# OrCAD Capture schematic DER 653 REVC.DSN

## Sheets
1 Misc: size A
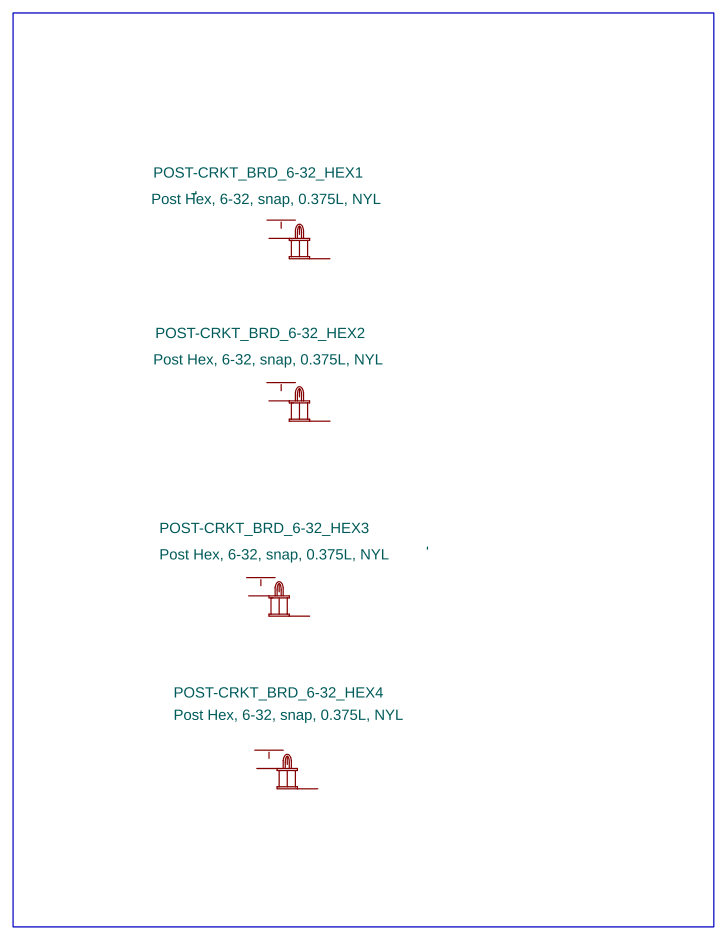
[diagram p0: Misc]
2 CONTROLLER AND INVERTER CKT: size D
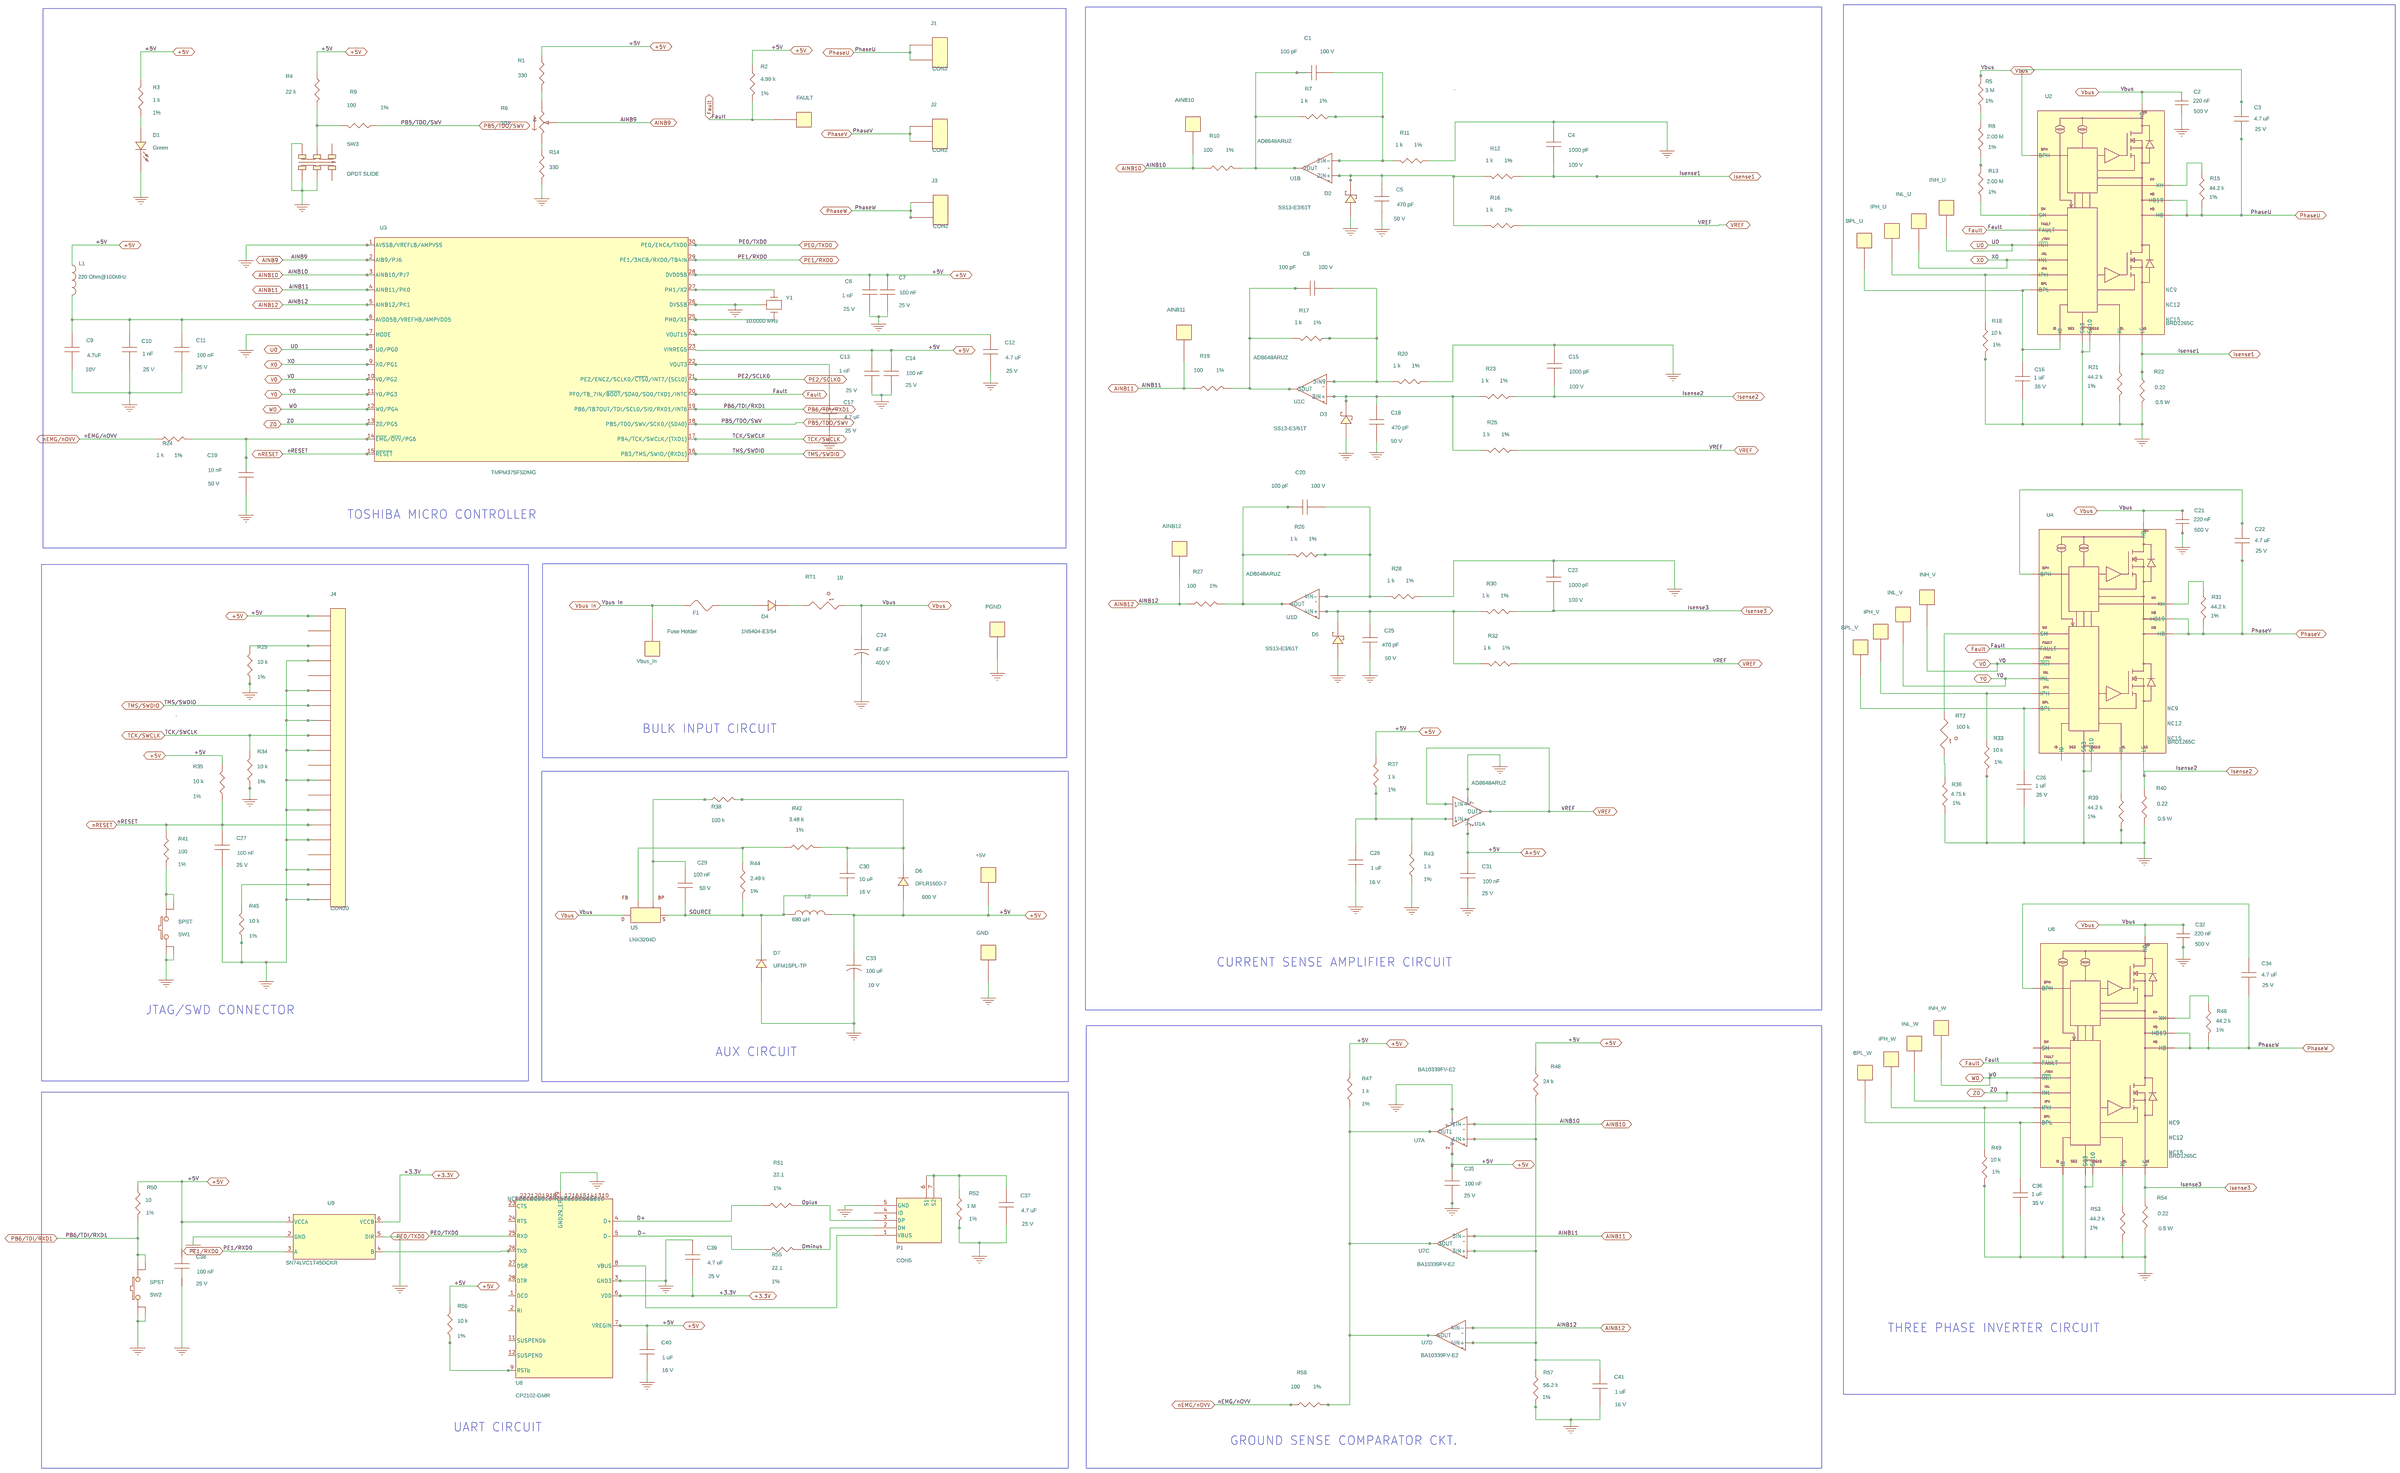
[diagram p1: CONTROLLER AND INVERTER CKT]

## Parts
sheet CONTROLLER AND INVERTER CKT
+5V  CON1  [pi_MillMax030d]
AINB10  CON1  [pi_MillMax030d]
AINB11  CON1  [pi_MillMax030d]
AINB12  CON1  [pi_MillMax030d]
BPL_U  CON1  [pi_MillMax030d]
BPL_V  CON1  [pi_MillMax030d]
BPL_W  CON1  [pi_MillMax030d]
C1  100 pF  [pismc0805]
C2  220 nF  [pismc1812]
C3  4.7 uF  [pismc1206]
C4  1000 pF  [pismc0603]
C5  470 pF  [pismc0603]
C6  1 nF  [pismc0603]
C7  100 nF  [pismc0603]
C8  100 pF  [pismc0805]
C9  4.7uF  [pismc0603]
C10  1 nF  [pismc0603]
C11  100 nF  [pismc0603]
C12  4.7 uF  [pismc0805]
C13  1 nF  [pismc0603]
C14  100 nF  [pismc0603]
C15  1000 pF  [pismc0603]
C16  1 uF  [pismc0603]
C17  4.7 uF  [pismc0805]
C18  470 pF  [pismc0603]
C19  10 nF  [pismc0603]
C20  100 pF  [pismc0805]
C21  220 nF  [pismc1812]
C22  4.7 uF  [pismc1206]
C23  1000 pF  [pismc0603]
C24  47 uF  [pipolcapclyd710ls300040]
C25  470 pF  [pismc0603]
C26  1 uF  [pismc0603]
C27  100 nF  [pismc0603]
C28  1 uF  [pismc0603]
C29  100 nF  [pismc0603]
C30  10 uF  [pismc0805]
C31  100 nF  [pismc0603]
C32  220 nF  [pismc1812]
C33  100 uF  [pipolcapclyd200ls80030]
C34  4.7 uF  [pismc1206]
C35  100 nF  [pismc0603]
C36  1 uF  [pismc0603]
C37  4.7 uF  [pismc0805]
C38  100 nF  [pismc0603]
C39  4.7 uF  [pismc0805]
C40  1 uF  [pismc0603]
C41  1 uF  [pismc0603]
D1  Green  [pi_sm_d_0603]
D2  SS13-E3/61T  [pismdo214ac12]
D3  SS13-E3/61T  [pismdo214ac12]
D4  1N5404-E3/54  [pidv300x200x060do15d0201ad]
D5  SS13-E3/61T  [pismdo214ac12]
D6  DFLR1600-7  [pismddflr120012]
D7  UFM15PL-TP  [pi_sm_sod-123_12]
F1  Fuse Holder  [fuse_e]
FAULT  CON1  [pi_MillMax030d]
GND  CON1  [pi_MillMax030d]
INH_U  CON1  [pi_MillMax030d]
INH_V  CON1  [pi_MillMax030d]
INH_W  CON1  [pi_MillMax030d]
INL_U  CON1  [pi_MillMax030d]
INL_V  CON1  [pi_MillMax030d]
INL_W  CON1  [pi_MillMax030d]
IPH_U  CON1  [pi_MillMax030d]
IPH_V  CON1  [pi_MillMax030d]
IPH_W  CON1  [pi_MillMax030d]
J1  CON2  [pi_conn_qc_tab_2pin_ls200]
J2  CON2  [pi_conn_qc_tab_2pin_ls200]
J3  CON2  [pi_conn_qc_tab_2pin_ls200]
J4  CON20  [pi_20p_2x10_Shrouded]
L1  220 Ohm@100MHz  [INDC2012X105N]
L2  680 uH  [pichoketokinvd345h453ls197d030]
P1  CON5  [TE_CONNECTIVITY_1734510-1]
PGND  CON1  [pi_MillMax030d]
R1  330  [pismr0603]
R2  4.99 k  [pismr0805]
R3  1 k  [pismr0603]
R4  22 k  [pismr0603]
R5  3 M  [pismr1206]
R6  10 k  [pi_vres_vertadj]
R7  1 k  [pismr0603]
R8  2.00 M  [pismr1206]
R9  100  [pismr0603]
R10  100  [pismr0603]
R11  1 k  [pismr0603]
R12  1 k  [pismr0603]
R13  2.00 M  [pismr1206]
R14  330  [pismr0603]
R15  44.2 k  [pismr0603]
R16  1 k  [pismr0603]
R17  1 k  [pismr0603]
R18  10 k  [pismr0603]
R19  100  [pismr0603]
R20  1 k  [pismr0603]
R21  44.2 k  [pismr0603]
R22  0.22  [pismr2010]
R23  1 k  [pismr0603]
R24  1 k  [pismr0603]
R25  1 k  [pismr0603]
R26  1 k  [pismr0603]
R27  100  [pismr0603]
R28  1 k  [pismr0603]
R29  10 k  [pismr0603]
R30  1 k  [pismr0603]
R31  44.2 k  [pismr0603]
R32  1 k  [pismr0603]
R33  10 k  [pismr0603]
R34  10 k  [pismr0603]
R35  10 k  [pismr0603]
R36  4.75 k  [pismr0805]
R37  1 k  [pismr0603]
R38  100 k  [pismr0805]
R39  44.2 k  [pismr0603]
R40  0.22  [pismr2010]
R41  100  [pismr0603]
R42  3.48 k  [pismr0402]
R43  1 k  [pismr0603]
R44  2.49 k  [pismr0402]
R45  10 k  [pismr0603]
R46  44.2 k  [pismr0603]
R47  1 k  [pismr0603]
R48  24 k  [pismr0805]
R49  10 k  [pismr0603]
R50  10  [pismr0603]
R51  22.1  [pismr0805]
R52  1 M  [pismr0805]
R53  44.2 k  [pismr0603]
R54  0.22  [pismr2010]
R55  22.1  [pismr0805]
R56  10 k  [pismr0603]
R57  56.2 k  [pismr0805]
R58  100  [pismr0603]
RT1  10  [pirad400x175ls250031]
RT2  100 k  [pismr0603]
SW1  SPST  [pi_switch_SKRPABE010]
SW2  SPST  [pi_switch_SKRPABE010]
SW3  DPDT SLIDE  [pi_switch_dpdt_slide_EG2209]
U1  AD8648ARUZ  [pi_sm_14TSSOP]  (sections A,B,C,D)
U2  BRD1265C  [pi_ic_insop_24C]
U3  TMPM375FSDMG  [pi_sm_30_ssop]
U4  BRD1265C  [pi_ic_insop_24C]
U5  LNK3204D  [pismso8dnshort5678]
U6  BRD1265C  [pi_ic_insop_24C]
U7  BA10339FV-E2  [pi_sm_14LSSOP]  (sections A,C,D)
U8  CP2102-GMR  [PI_SM_28-VFQFN_EP]
U9  SN74LVC1T45DCKR  [pi_sm_sot_363]
Vbus_In  CON1  [pi_MillMax030d]
Y1  10.0000 MHz  [pi_ic_cer_resonator]
sheet Misc
POST-CRKT_BRD_6-32_HEX1  Post Hex, 6-32, snap, 0.375L, NYL  [pimtgholed156]
POST-CRKT_BRD_6-32_HEX2  Post Hex, 6-32, snap, 0.375L, NYL  [pimtgholed156]
POST-CRKT_BRD_6-32_HEX3  Post Hex, 6-32, snap, 0.375L, NYL  [pimtgholed156]
POST-CRKT_BRD_6-32_HEX4  Post Hex, 6-32, snap, 0.375L, NYL  [pimtgholed156]

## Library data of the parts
+5V AINB10-AINB12 BPL_U BPL_V BPL_W FAULT GND INH_U INH_V INH_W INL_U INL_V INL_W IPH_U IPH_V IPH_W PGND Vbus_In = Term_1Pin: Part Number: 35-00387-00
C1 C8 C20 = CAP_NP_v2: Disp_Voltage: 100 V; Part Number: 20-00581-00; Voltage: 100 V
C2 C21 C32 = CAP_NP: Disp_Voltage: 500 V; Part Number: 20-08903-00; ROOM: 1; Voltage: 500 V
C3 C22 C34 = CAP_NP_v2: Disp_Voltage: 25 V; Part Number: 20-09136-00; Voltage: 25 V
C4 C15 C23 = CAP_NP_v2: Disp_Voltage: 100 V; Part Number: 20-00712-00; Voltage: 100 V
C5 C18 C25 = CAP_NP_v2: Disp_Voltage: 50 V; Part Number: 20-00510-00; Voltage: 50 V
C6 C10 C13 = CAP_NP_v2: Disp_Voltage: 25 V; Part Number: 20-08948-00; Voltage: 25 V
C7 C11 C14 C27 C31 C35 C38 = CAP_NP_v2: Disp_Voltage: 25 V; Part Number: 20-01050-00; Voltage: 25 V
C9 = CAP_NP_v2: Disp_Voltage: 10V; Part Number: 20-08591-00; Voltage: 10 V
C12 C17 C37 C39 = CAP_NP_v2: Disp_Voltage: 25 V; Part Number: 20-09137-00; Voltage: 16 V
C16 C26 C36 = CAP_NP_v2: ALT_SYMBOLS: pismc0603_1; Disp_Voltage: 35 V; FPLIST: pismc0603,pismc0603_1; Part Number: 20-09161-00; ROOM: 4; Voltage: 35 V
C19 = CAP_NP_v2: Disp_Voltage: 50 V; Part Number: 20-01051-00; Voltage: 50V
C24 = CAP_POL: Disp_Voltage: 400 V; Part Number: 20-00489-00; Voltage: 400 V
C28 C40 C41 = CAP_NP_v2: Disp_Voltage: 16 V; Part Number: 20-01020-00; Voltage: 16 V
C29 = CAP_NP_v2: Disp_Voltage: 50 V; Part Number: 20-00936-00; Voltage: 50 V
C30 = CAP_NP_v2: Disp_Voltage: 16 V; Part Number: 20-08964-00; Voltage: 16 V
C33 = CAP_POL: Disp_Voltage: 10 V; Part Number: 20-00065-00; Voltage: 10 V
D1 = LED: Part Number: 15-00955-00
D2 D3 D5 = DIODE_SCHOTTKY: Part Number: 15-01054-00
D4 = DIODE: ALT_SYMBOLS: pidax800x225060do15do201ad,pidv300x200x060do14wbead; FPLIST: pidv300x200x060do15d0201ad,pidax800x225060do15do201ad,pidv300x200x060do14wbead; Part Number: 15-00796-00
D6 = DIODE: Disp_Voltage: 600 V; Part Number: 15-00826-00
D7 = DIODE: Part Number: 15-00927-00
F1 = FUSE: Part Number: 35-00334-00
J1-J3 = CON2: Part Number: 35-00281-00
J4 = CON20: Part Number: 35-00388-00
L1 = INDUCTOR_BEAD: Part Number: 30-00431-00
L2 = INDUCTOR: Part Number: 30-00025-00
P1 = USB_MINI_B_R_A_DIP: Part Number: 35-00335-00
R1 R14 = R: Part Number: 05-01676-00
R2 = R: Disp_Tol: 1%; Part Number: 05-03373-00
R3 R7 R11 R12 R16 R17 R20 R23-R26 R28 R30 R32 R37 R43 R47 = R: Disp_Tol: 1%; Part Number: 05-01078-00
R4 = R: Part Number: 05-01720-00
R5 = R: Disp_Tol: 1%; Part Number: 05-05562-00; ROOM: 4
R6 = POT: Part Number: 05-03510-00
R8 R13 = R: Disp_Tol: 1%; Part Number: 05-03156-00; ROOM: 4
R9 R10 R19 R27 R41 R58 = R: Disp_Tol: 1%; Part Number: 05-00982-00
R15 R21 R31 R39 R46 R53 = R: Disp_Tol: 1%; Part Number: 05-03246-00
R18 R29 R33-R35 R45 R49 R56 = R: Disp_Tol: 1%; Part Number: 05-03182-00
R22 R40 R54 = R: Disp_Power: 0.5 W; Part Number: 05-03164-00
R36 = R: Disp_Tol: 1%; Part Number: 05-03371-00
R38 = R: Part Number: 05-01567-00
R42 = R: Disp_Tol: 1%; Part Number: 05-05883-00
R44 = R: Disp_Tol: 1%; Part Number: 05-05866-00; Tol: 1%
R48 = R: Part Number: 05-01552-00
R50 = R: Disp_Tol: 1%; Part Number: 05-00886-00
R51 R55 = R: Disp_Tol: 1%; Part Number: 05-00525-00
R52 = R: Disp_Tol: 1%; Part Number: 05-00876-00
R57 = R: Disp_Tol: 1%; Part Number: 05-00756-00
RT1 = THERMISTOR: ALT_SYMBOLS: pirad400x175ls250040_h; FPLIST: pirad400x175ls250031,pirad400x175ls250040_h; Part Number: 90-00013-00
RT2 = THERMISTOR: Part Number: 90-00063-00
SW1 SW2 = SW_PUSHBUTTON-SPST_1-2_3-4: Part Number: 66-00216-00
SW3 = SW_SLIDE-DPDT: Part Number: 66-00212-00
U1 = TL084_Hetero: Part Number: 45-00438-00
U2 U4 U6 = BridgeSwitch_1265C: Part Number: 10-01087-00
U3 = TMPM375FSDMG: Part Number: 45-00433-00
U5 = LNK32XX_8C: Part Number: 10-00950-00
U7 = Comparator_Quad_Hetero: Part Number: 45-00439-00
U8 = CP2102-GMR: Part Number: 45-00442-00
U9 = SN74LVC1T45DCKR: Part Number: 45-00440-00
Y1 = CRYSTAL_RESONATOR: Part Number: 66-00215-00
POST-CRKT_BRD_6-32_HEX1-POST-CRKT_BRD_6-32_HEX4 = POST_CRKT_BRD_6-32_HEX: Part Number: 76-00003-00

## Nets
+3.3V: C39.2 U8.6(VDD) U9.6(VCCB)
+5V: +5V.1 C6.1 C7.1 C13.1 C14.1 C31.1 C33.1 C35.1 C38.1 C40.1 D6.2 J4.1 L1.1 L2.2 R1.1 R2.1 R3.2 R4.1 R35.2 R37.2 R47.2 R48.1 R50.1 R56.2 U1.4(V+) U3.23(VINREG5) U3.28(DVDD5B) U7.3(V+) U8.7(VREGIN) U9.1(VCCA)
GND: C2.2 C4.1 C5.2 C6.2 C7.2 C9.2 C10.2 C11.2 C12.2 C13.2 C14.2 C15.1 C16.2 C17.2 C18.2 C19.2 C21.2 C23.1 C24.2 C25.2 C26.2 C27.2 C28.2 C31.2 C32.2 C33.2 C35.2 C36.2 C37.2 C38.2 C39.1 C40.2 C41.2 D1.1(CATHODE) D2.2 D3.2 D5.2 D7.2 GND.1 J4.4 J4.6 J4.8 J4.10 J4.12 J4.14 J4.16 J4.18 J4.20 P1.5(GND) PGND.1 R11.1 R14.2 R18.2 R20.1 R21.2 R22.2 R28.1 R29.1 R33.2 R34.1 R36.1 R39.2 R40.2 R43.1 R45.1 R49.2 R52.2 R53.2 R54.2 R57.2 SW1.3 SW1.4 SW2.3 SW2.4 SW3.1 SW3.4 SW3.5 U1.11(V-) U2.3(SG3) U2.10(SG10) U3.1(AVSSB/VREFLB/AMPVSS) U3.7(MODE) U3.26(DVSSB) U4.3(SG3) U4.10(SG10) U6.3(SG3) U6.10(SG10) U6.11(ID) U7.12(V-) U8.3(GND3) U8.29(GND29_EP) U9.2(GND) U9.5(DIR) Y1.2
V0: INH_V.1 U3.10(V0/PG2) U4.6(~{INH})
Vbus: C2.1 C21.1 C24.1 C32.1 R5.1 RT1.2 U2.25(HD) U4.25(HD) U5.4(D) U6.25(HD)
Vbus In: F1.1 Vbus_In.1
AINB9: R6.2(WIPER) U3.2(AIB9/PJ6)
AINB10: AINB10.1 R10.1 U3.3(AINB10/PJ7) U7.4(1IN-)
AINB11: AINB11.1 R19.1 U3.4(AINB11/PK0) U7.8(3IN-)
AINB12: AINB12.1 R27.1 U3.5(AINB12/PK1) U7.10(4IN-)
D+: R51.1 U8.4(D+)
D-: R55.1 U8.5(D-)
Dminus: P1.2(DM) R55.2
Dplus: P1.3(DP) R51.2
Fault: FAULT.1 R2.2 U2.7(FAULT) U3.20(PF0/TB_7IN/~{BOOT}/SDA0/SO0/TXD1/INTC) U4.7(FAULT) U6.7(FAULT)
Isense1: C4.2 R12.1 R22.1 U2.24(LS)
Isense2: C15.2 R23.1 R40.1 U4.24(LS)
Isense3: C23.2 R30.1 R54.1 U6.24(LS)
nEMG/nOVV: R24.1 R58.1
nRESET: C27.1 J4.15 R35.1 R41.1 U3.15(~{RESET})
PB5/TDO/SWV: R9.1 U3.18(PB5/TD0/SWV/SCK0/(SDA0))
PB6/TDI/RXD1: R50.2 SW2.1 SW2.2 U3.19(PB6/TB7OUT/TDI/SCL0/SI0/RXD1/INT6)
PE0/TXD0: U3.30(PE0/ENCA/TXD0) U8.25(RXD)
PE1/RXD0: U3.29(PE1/3NCB/RXD0/TB4IN) U9.3(A)
PE2/SCLK0: U3.21(PE2/ENCZ/SCLK0/~{CTS0}/INT7/(SCL0))
PhaseU: C3.2 J1.1 J1.2 R15.2 U2.16(HB) U2.19(HB19)
PhaseV: C22.2 J2.1 J2.2 R31.2 U4.16(HB) U4.19(HB19)
PhaseW: C34.2 J3.1 J3.2 R46.2 U6.16(HB) U6.19(HB19)
SOURCE: C29.2 C30.2 D7.1 L2.1 R44.2 U5.5(S) U5.6(SOURCE) U5.7(SOURCE) U5.8(SOURCE)
TCK/SWCLK: J4.9 R34.2 U3.17(PB4/TCK/SWCLK/(TXD1))
TMS/SWDIO: J4.7 U3.16(PB3/TMS/SWIO/(RXD1))
U0: INH_U.1 U2.6(~{INH}) U3.8(U0/PG0)
VREF: R16.1 R25.1 R32.1 U1.1(OUT1) U1.2(1IN-)
W0: INH_W.1 U3.12(W0/PG4) U6.6(~{INH})
X0: INL_U.1 U2.5(INL) U3.9(X0/PG1)
Y0: INL_V.1 U3.11(Y0/PG3) U4.5(INL)
Z0: INL_W.1 U3.13(Z0/PG5) U6.5(INL)
N11220086: C19.1 R24.2 U3.14(~{EMG}/~{OVV}/PG6)
N11227943: C9.1 C10.1 C11.1 L1.2 U3.6(AVDD5B/VREFHB/AMPVDD5)
N11232120: U3.27(PM1/X2) Y1.1
N11232225: U3.25(PM0/X1) Y1.3
N11232827: C17.1 U3.22(VOUT3)
N11233445: C12.1 U3.24(VOUT15)
N11251291: D1.2(ANODE) R3.1
N11255215: R4.2 R9.2 SW3.2
N11983160: R1.2 R6.1(CCW)
N11983204: R6.3(CW) R14.1
N11990346: J4.3 R29.2
N11990582: J4.19 R45.2
N12027525: C3.1 U2.14(BPH)
N12027529: R15.1 U2.13(XH)
N12027579: R8.1 R13.2
N12027695: IPH_U.1 R18.1 U2.2(IPH)
N12027757: BPL_U.1 C16.1 U2.4(BPL) U2.11(ID)
N12027769: R21.1 U2.1(XL)
N12027985: RT2.1 U4.8(SM)
N12028197: C22.1 U4.14(BPH)
N12028205: R31.1 U4.13(XH)
N12028339: IPH_V.1 R33.1 U4.2(IPH)
N12028369: BPL_V.1 C26.1 U4.4(BPL)
N12028389: R39.1 U4.1(XL)
N12028721: C34.1 U6.14(BPH)
N12028725: R46.1 U6.13(XH)
N12028855: IPH_W.1 R49.1 U6.2(IPH)
N12028877: BPL_W.1 C36.1 U6.4(BPL)
N12028909: R53.1 U6.1(XL)
N12056627: R13.1 U2.8(SM)
N12134803: C1.1 R7.2 R10.2 U1.7(2OUT)
N12134815: C1.2 R7.1 R11.2 U1.6(2IN-)
N12135029: C5.1 D2.1 R12.2 R16.2 U1.5(2IN+)
N12135163: C8.1 R17.2 R19.2 U1.8(3OUT)
N12135175: C8.2 R17.1 R20.2 U1.9(3IN9)
N12135393: C18.1 D3.1 R23.2 R25.2 U1.10(3IN+)
N12135507: C20.1 R26.2 R27.2 U1.14(4OUT)
N12135519: C20.2 R26.1 R28.2 U1.13(4IN-)
N12135733: C25.1 D5.1 R30.2 R32.2 U1.12(4IN+)
N12135901: C28.1 R37.1 R43.2 U1.3(1IN+)
N12173083: C41.1 R48.2 R57.1 U7.5(1IN+) U7.9(3IN+) U7.11(4IN+)
N12173113: R47.1 R58.2 U7.2(OUT1) U7.13(4OUT) U7.14(3OUT)
N12190188: R5.2 R8.2
N12206798: C29.1 R38.1 U5.1(BP)
N12206810: C30.1 D6.1 R38.2 R42.2
N12206840: R42.1 R44.1 U5.2(FB)
N12208110: D4.2 F1.2
N12208114: D4.1 RT1.1
N12209410: C37.1 P1.6(S1) P1.7(S2) R52.1
N12209768: P1.1(VBUS) U8.8(VBUS)
N12209854: U8.26(TXD) U9.4(B)
N12210084: R56.1 U8.9(RSTb)
N12217120: R41.2 SW1.1 SW1.2
N12236869: R36.2 RT2.2

Not connected (* = marked no-connect by the designer): J4 2 5 11 13 17; P1 4(ID); POST-CRKT_BRD_6-32_HEX1 1; POST-CRKT_BRD_6-32_HEX2 1; POST-CRKT_BRD_6-32_HEX3 1; POST-CRKT_BRD_6-32_HEX4 1; SW3 3 6; U2 9(NC9) 12(NC12) 15(NC15); U4 9(NC9) 11(ID) 12(NC12) 15(NC15); U6 8(SM) 9(NC9) 12(NC12) 15(NC15); U8 1(DCD) 2(RI) 10(NC10) 11(SUSPENDb) 12(SUSPEND) 13(NC13) 14(NC14) 15(NC15) 16(NC16) 17(NC17) 18(NC18) 19(NC19) 20(NC20) 21(NC21) 22(NC22) 23(CTS) 24(RTS) 27(DSR) 28(DTR)

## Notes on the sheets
sheet 2
- TOSHIBA MICRO CONTROLLER
- BULK INPUT CIRCUIT
- CURRENT SENSE AMPLIFIER CIRCUIT
- JTAG/SWD CONNECTOR
- AUX CIRCUIT
- THREE PHASE INVERTER CIRCUIT
- UART CIRCUIT
- GROUND SENSE COMPARATOR CKT.
